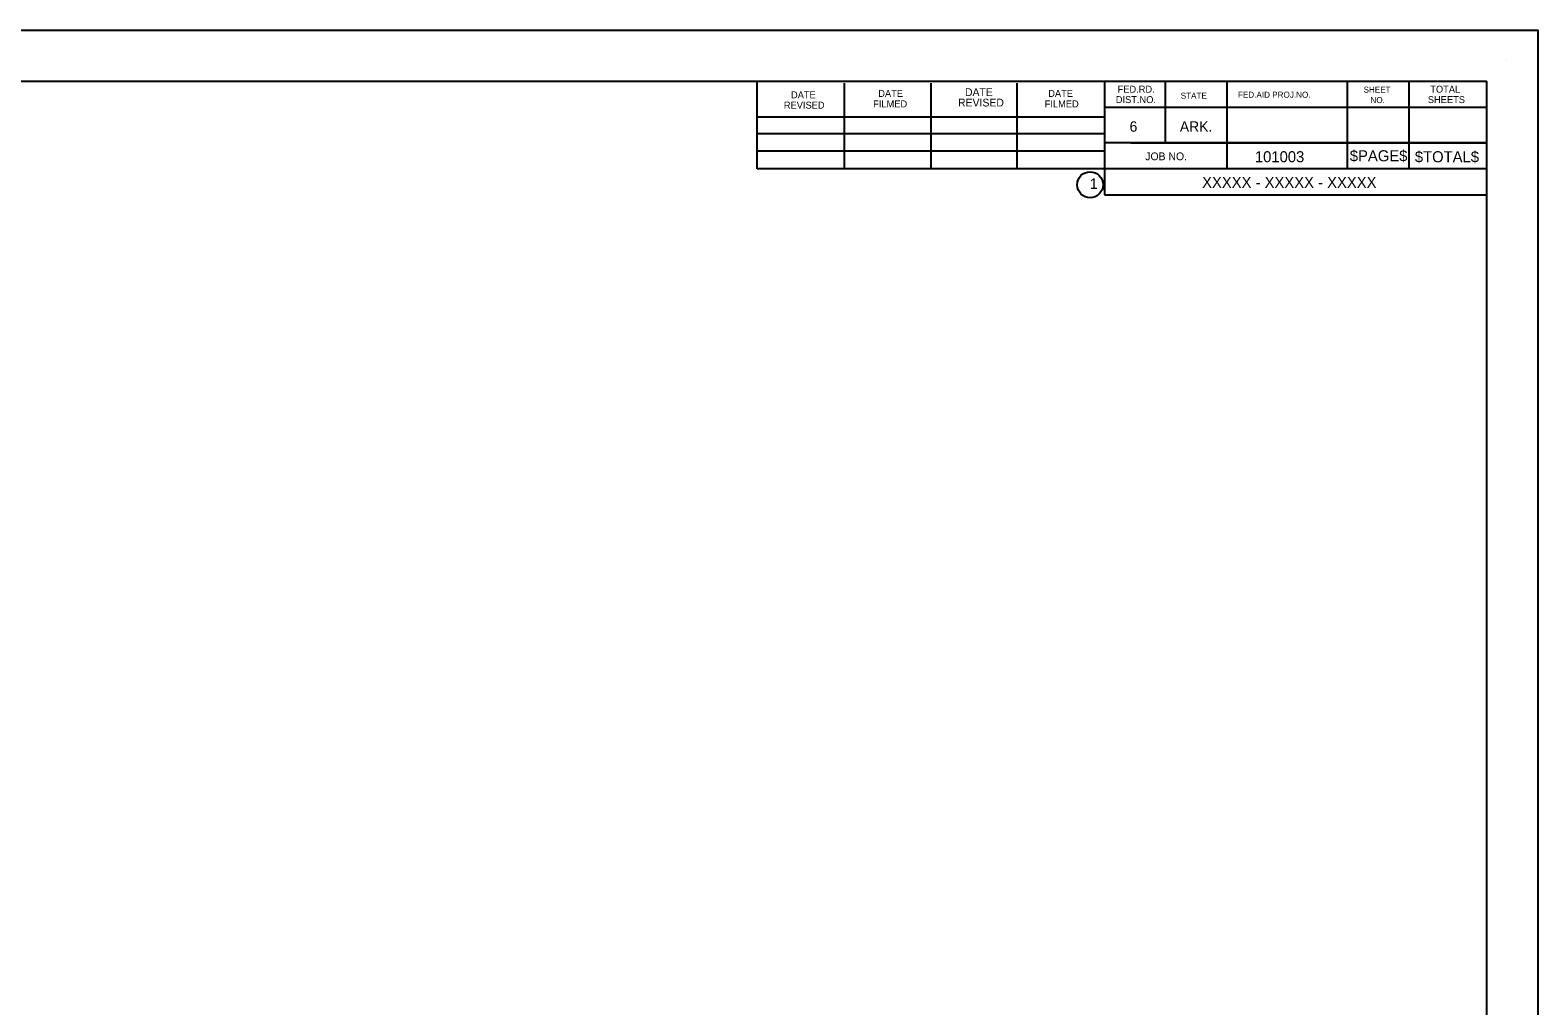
# Model space of a CAD drawing. Extents: x 16 to 1228740, y 11 to 152440.
# Drawn here: x 17.074 to 18.49, y 11.626 to 12.543 of the extents above; entities that cross this region are included whole.
import ezdxf

# ---------------------------------------------------------------- set-up
doc = ezdxf.new("R2010")
doc.units = 0
doc.layers.add('B_Copy In', color=7, linetype='Continuous')
doc.layers.add('R_Border', color=7, linetype='Continuous')

msp = doc.modelspace()

# ---------------------------------------------------------------- linework, layer by layer
at = {"layer": 'R_Border'}
for p, q in [((18.4604, 12.514), (18.4604, 12.514)), ((15.7833, 12.4948), (18.4422, 12.4948)), ((17.7567, 12.4124), (17.7567, 12.4948)), ((17.8389, 12.4124), (17.8389, 12.4931)), ((17.9202, 12.4124), (17.9202, 12.4931)), ((18.0009, 12.4124), (18.0009, 12.4931)), ((18.083, 12.4948), (18.083, 12.3881)), ((18.14, 12.4948), (18.14, 12.4369)), ((18.1979, 12.4948), (18.1979, 12.4124)), ((18.311, 12.4948), (18.311, 12.4124)), ((18.3689, 12.4948), (18.3689, 12.4124)), ((18.4422, 10.7576), (18.4422, 12.4948)), ((18.4422, 12.4703), (18.083, 12.4703)), ((18.4422, 12.4704), (18.4422, 12.4704)), ((17.7567, 12.4613), (18.083, 12.4613)), ((17.7567, 12.4458), (18.083, 12.4458)), ((17.7567, 12.4124), (17.7567, 12.4296)), ((17.7567, 12.4296), (18.083, 12.4296)), ((18.4422, 12.4369), (18.083, 12.4369)), ((18.1077, 12.4369), (18.4422, 12.4369)), ((18.4422, 12.4124), (17.7567, 12.4124)), ((18.083, 12.3881), (18.4422, 12.3881))]:
    msp.add_line(p, q, dxfattribs=at)
msp.add_lwpolyline([(15.6569, 12.5428), (18.4903, 12.5428), (18.4903, 10.7095), (15.6569, 10.7095)], close=True, dxfattribs=at)
msp.add_circle((18.0696, 12.3976), 0.0122, dxfattribs=at)

# ---------------------------------------------------------------- texts
at = {"layer": 'B_Copy In'}
msp.add_text('XXXXX - XXXXX - XXXXX', height=0.0104, dxfattribs=at).set_placement((18.1748, 12.3946))
at = {"layer": 'R_Border'}
for s, height, p in [('DATE', 0.00652, (17.7885, 12.4788)), ('DATE', 0.00652, (17.8705, 12.4801)), ('DATE', 0.00733, (17.952, 12.4809)), ('DATE', 0.00652, (18.0302, 12.4801)), ('DIST.NO.', 0.00652, (18.0937, 12.4743)), ('FED.RD.', 0.00652, (18.0954, 12.4841)), ('STATE', 0.0057, (18.1547, 12.4784)), ('FED.AID PROJ.NO.', 0.0057, (18.2085, 12.4793)), ('SHEET', 0.0057, (18.3265, 12.4841)), ('SHEETS', 0.00652, (18.3869, 12.4743)), ('TOTAL', 0.00652, (18.3892, 12.4841)), ('REVISED', 0.00652, (17.7818, 12.4691)), ('FILMED', 0.00652, (17.8657, 12.4703)), ('REVISED', 0.00733, (17.9455, 12.4711)), ('FILMED', 0.00652, (18.0269, 12.4703)), ('NO.', 0.0057, (18.333, 12.4743)), ('6', 0.00977, (18.1067, 12.4474)), ('ARK.', 0.00977, (18.1539, 12.4474)), ('JOB NO.', 0.00733, (18.1214, 12.4206)), ('101003', 0.0104, (18.2244, 12.4187)), ('$PAGE$', 0.0104, (18.3136, 12.4196)), ('$TOTAL$', 0.0104, (18.3747, 12.4187)), ('1', 0.00977, (18.0693, 12.3937))]:
    msp.add_text(s, height=height, dxfattribs=at).set_placement(p)

doc.saveas('drawing.dxf')
